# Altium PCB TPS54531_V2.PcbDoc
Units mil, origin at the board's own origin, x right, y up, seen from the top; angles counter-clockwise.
Board outline 1035 x 775 mil, 2 copper layers (Top Layer, Bottom Layer); 21 components, 10 nets, 49 pads, 25 vias.
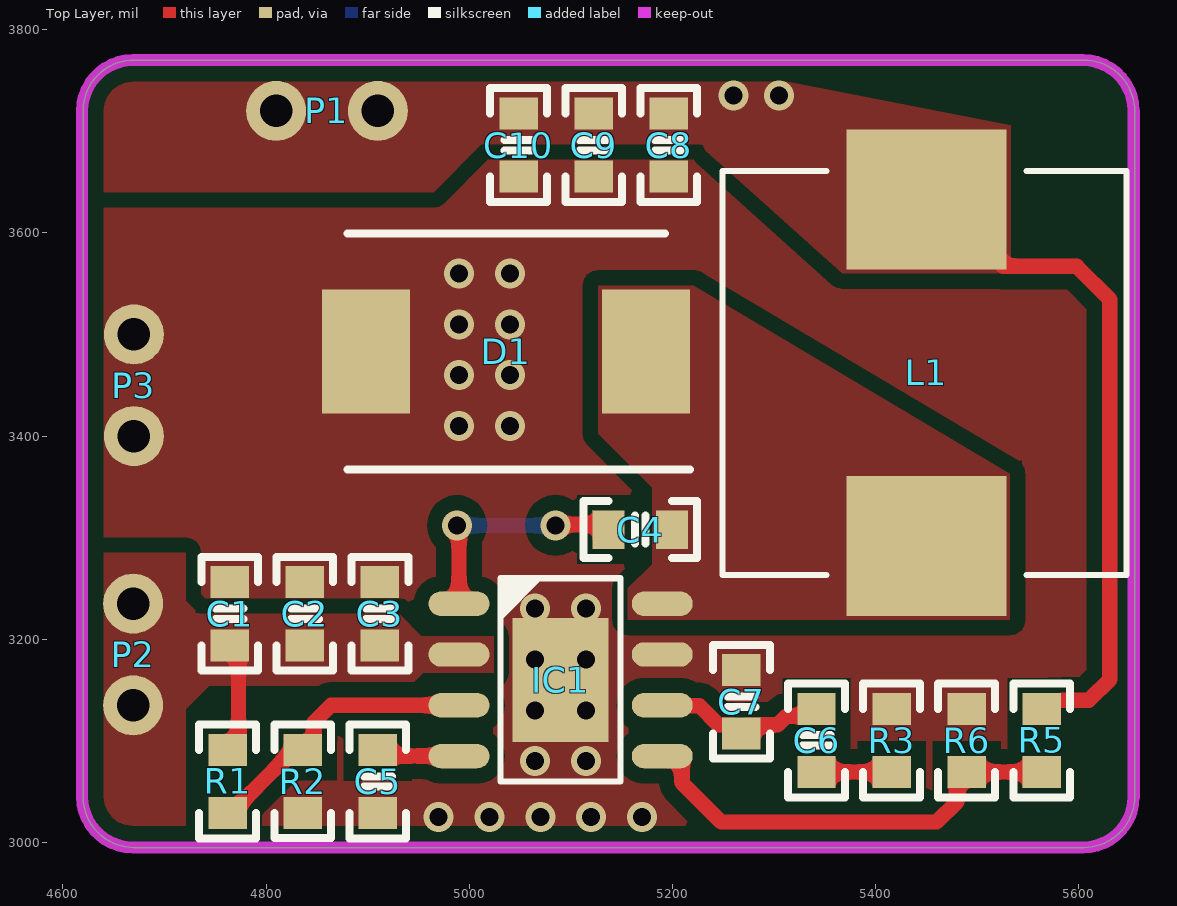
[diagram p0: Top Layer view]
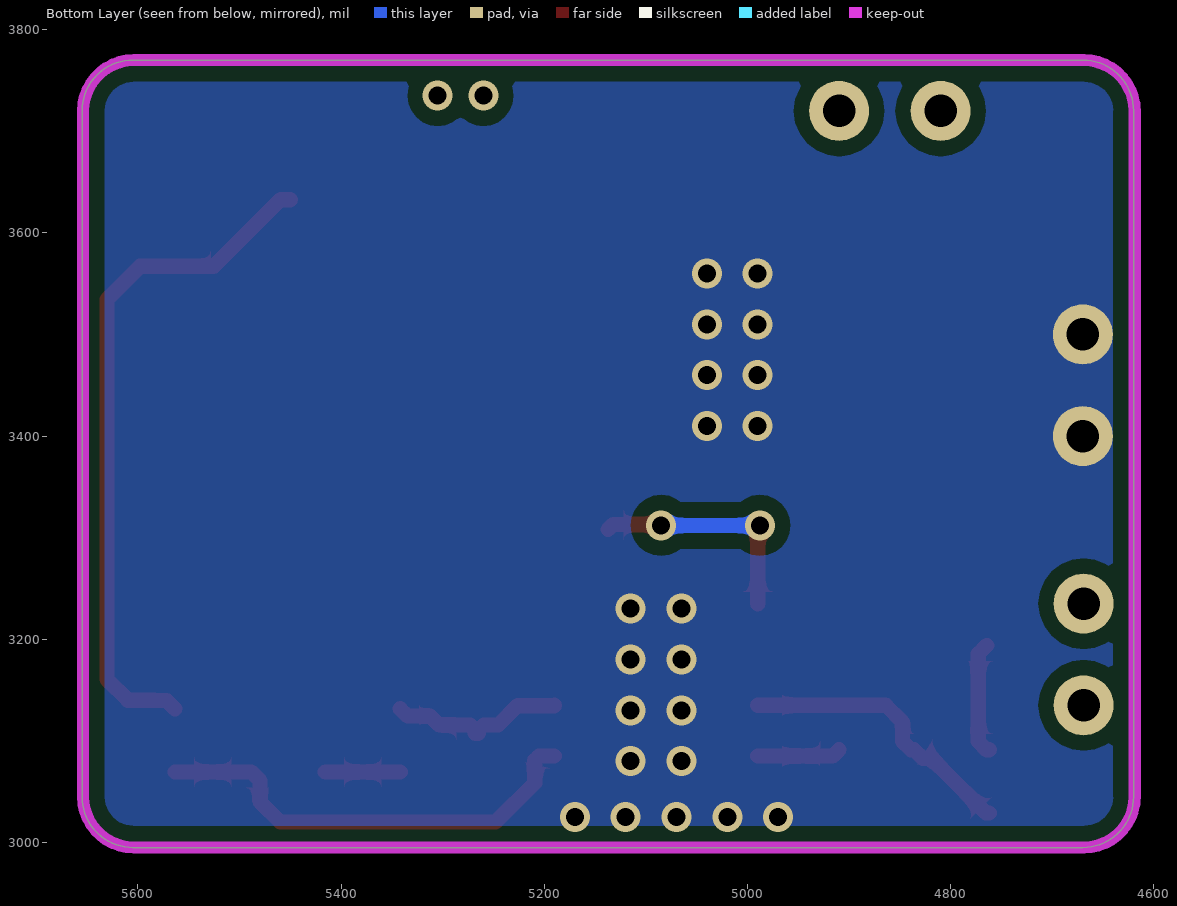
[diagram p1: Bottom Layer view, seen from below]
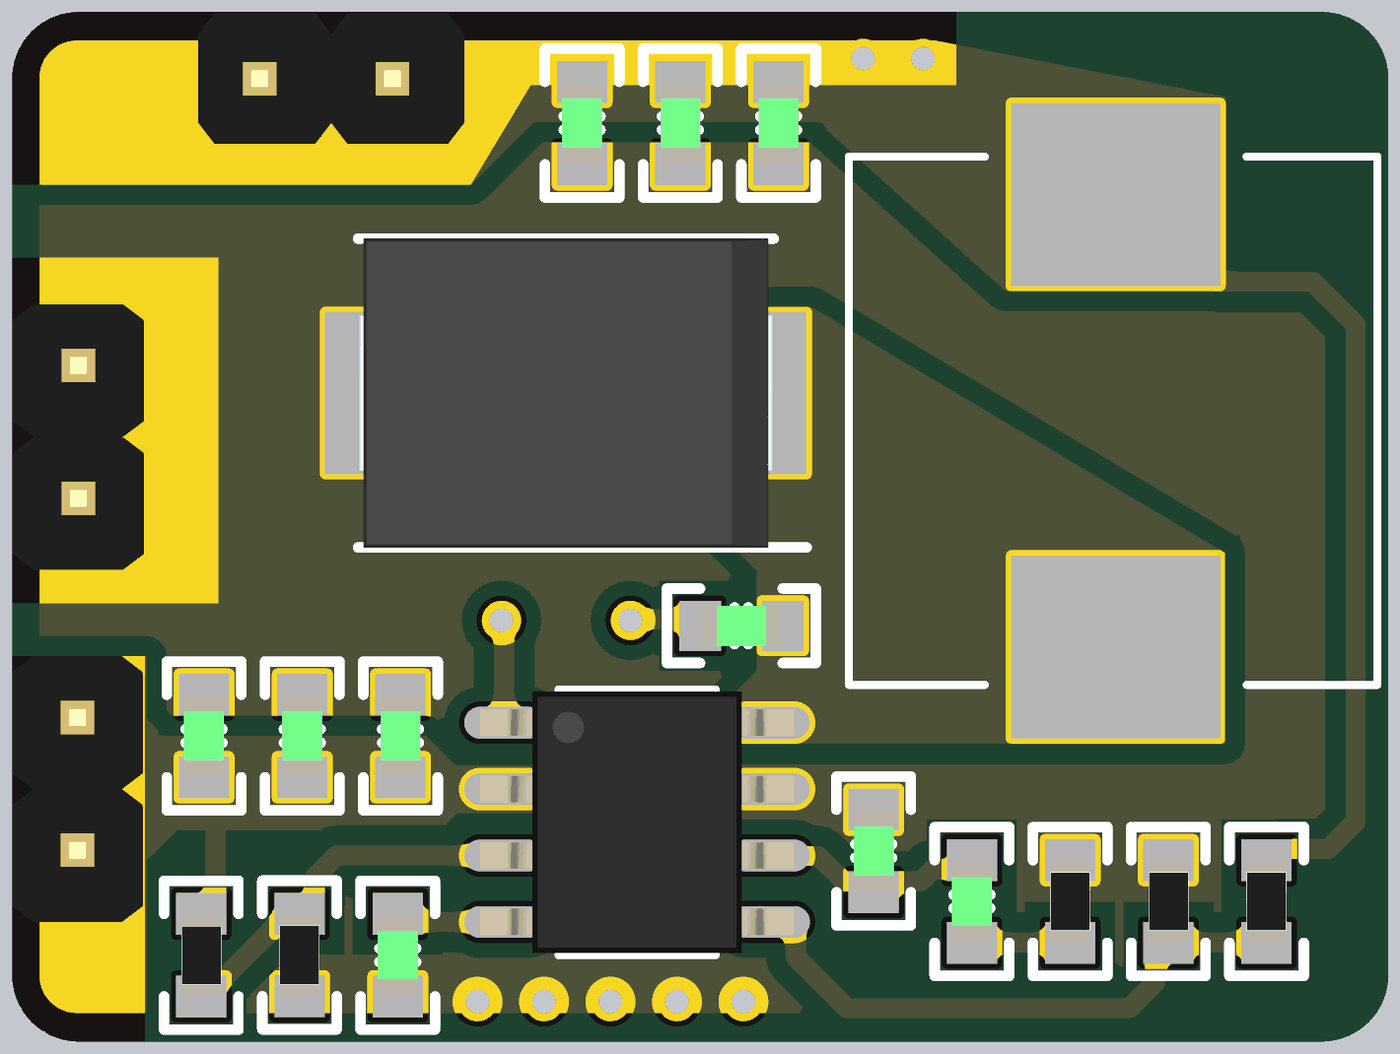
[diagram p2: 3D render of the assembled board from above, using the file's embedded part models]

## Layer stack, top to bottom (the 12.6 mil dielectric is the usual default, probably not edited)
Top Solder: solder mask 0.4, Solder Resist, Dk 3.5
Top Layer: signal copper 1.4
Dielectric 1: dielectric 12.6, FR-4, Dk 4.8
Bottom Layer: signal copper 1.4
Bottom Solder: solder mask 0.4, Solder Resist, Dk 3.5

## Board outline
4620,3045 ccw(c4670,3045) 4670,2995 4780,2995 5605,2995 ccw(c5605,3045) 5655,3045 5655,3720 ccw(c5605,3720) 5605,3770 4670,3770 ccw(c4670,3720) 4620,3720

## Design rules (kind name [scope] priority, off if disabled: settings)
Clearance [All] p1: gap=10 ignorepadtopadclearanceinfootprint=FALSE except(0: Arc-Hole Track-Hole SMDPad-Hole THPad-Hole Via-Hole Fill-Hole Poly-Hole Region-Hole Text-Hole; 15: Arc-Fill Arc-Poly Arc-Region Track-Fill Track-Poly Track-Region SMDPad-Fill SMDPad-Poly SMDPad-Region THPad-Fill THPad-Poly THPad-Region Via-Fill Via-Poly Via-Region Fill-Fill Fill-Poly Fill-Region Poly-Poly Poly-Region Region-Region)
PlaneConnect [All] p1: planeconnectstyle=Direct reliefexpansion=20 reliefentries=4 reliefconductorwidth=10 reliefairgap=10
PolygonConnect [All] p1: connectstyle=Direct reliefconductorwidth=10 reliefentries=4 polygonreliefangle="90 Angle" airgapwidth=10
RoutingVias [All] p1: holewidth=17.72 width=29.53 viastyle="Through Hole" minholewidth=17.72 minwidth=29.53 maxholewidth=17.72 maxwidth=29.53
SolderMaskExpansion [All] p1: expansion=4 istentingtop=FALSE
Width [All] p1: maxlimit=100 minlimit=10 preferedwidth=15
29 further rules are at their usual default settings.

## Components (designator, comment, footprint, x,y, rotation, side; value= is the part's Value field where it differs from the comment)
C1 "4.7uF" CAP-0603 4764.28,3225 r270 top
C2 "4.7uF" CAP-0603 4838.17,3225 r270 top
C3 "100nF" CAP-0603 4912.05,3225 r270 top
C4 "100nF" CAP-0603 5168.44,3307.95 r0 top
C5 "10nF" CAP-0603 4910,3060 r90 top
C6 "2200pF" CAP-0603 5341.83,3100.42 r90 top
C7 "22pF" CAP-0603 5267.95,3138.42 r270 top
C8 "47uF" CAP-0603 5196.44,3686.38 r90 top
C9 "47uF" CAP-0603 5122.55,3686.38 r90 top
C10 "100nF" CAP-0603 5048.67,3686.38 r90 top
D1 "SS54" DO-214AB 5036.45,3483.16 r180 top
IC1 "TPS54531DDA" SOIC_8_PAD 5090,3160 r270 top
L1 "4.7uH 5A" L-10040 5450,3462.31 r90 top
P1 "HDR1x2_2.54" HDR1X2_2.54_180 4810,3720 r90 top
P2 "HDR1x2_2.54" HDR1X2_2.54_180 4669.28,3235 r0 top
P3 "HDR1x2_2.54" HDR1X2_2.54_180 4670,3500 r0 top
R1 "665k" R-0603 4762.23,3060 r90 top
R2 "130k" R-0603 4836.12,3060.12 r90 top
R3 "37.4k" R-0603 5415.72,3100.42 r270 top
R5 "10.2k" R-0603 5563.48,3100.42 r90 top
R6 "1.96k" R-0603 5489.6,3100.42 r270 top

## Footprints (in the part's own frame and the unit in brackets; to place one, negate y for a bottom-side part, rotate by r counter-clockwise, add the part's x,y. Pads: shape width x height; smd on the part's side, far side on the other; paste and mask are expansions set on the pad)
CAP-0603 [mm]
  rect 0.8x0.96 smd: 1(-0.79,0) 2(0.79,0)
  silkscreen extent -1.42,-0.71 1.42,0.71, body extent -0.76,-0.39 0.76,0.39, height 0.9
DO-214AB [mm]
  rect 2.2x3.1 smd: 1(3.5,0) 2(-3.5,0)
  silkscreen extent -4.6,-2.95 3.97,2.95, body extent -3.97,-2.95 3.97,2.95, height 2.5
HDR1X2_2.54_180 [mm]
  round 1.5 hole 0.813: 1(0,0) 2(0,-2.54)
  body extent -1.25,-3.81 1.25,1.27, height 8.2
L-10040 [mm] "10.1*11.6*4.0MM(长*宽*高)"
  rect 3.5x4 smd: 1(-4.326,0) 2(4.326,0)
  silkscreen extent -5.05,-5 5.05,5.1, body extent -5,-5 5,5.08, height 4
R-0603 [mm]
  rect 0.8x0.96 smd: 1(-0.79,0) 2(0.79,0)
  silkscreen extent -1.42,-0.71 1.42,0.71, body extent -0.76,-0.38 0.76,0.38, height 0.41
SOIC_8_PAD [mil]
  oval 24x60 smd: 1(-75,-100) 2(-25,-100) 3(25,-100) 4(75,-100) 5(75,100) 6(25,100) 7(-25,100) 8(-75,100)
  rect 122.05x94.49 smd: 9(0,0)
  silkscreen extent -100,-59 100,59, body extent -98,-118 98,118, height 71

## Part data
C1 C2 C3 C4 C5 C6 C7 C8 C9 C10: library part CAP, "贴片电容", Package=0402, SuppliersPartNumber=C52923
D1: library part DIODE, "肖特基二极管", Package=SMA(DO-214AC), SuppliersPartNumber=C22452
IC1: "集成稳压芯片", Manufacturer_Name="Texas Instruments", Mouser Part Number=595-TPS54531DDA
L1: library part INDUCTOR, "电感", Package=0402, SuppliersPartNumber=C32041
P1 P2 P3: "Header"
R1 R2 R3 R5 R6: library part RES, "贴片电阻", Package=0805, SuppliersPartNumber=C17798

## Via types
v1: diameter 29.53, hole 17.72, Top Layer to Bottom Layer, 25 vias

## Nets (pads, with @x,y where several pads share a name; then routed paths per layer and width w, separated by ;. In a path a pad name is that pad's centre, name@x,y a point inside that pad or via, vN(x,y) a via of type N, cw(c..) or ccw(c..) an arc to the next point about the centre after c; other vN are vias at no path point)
5V: C8.2 C9.2 C10.2 L1.2 P1.1 P1.2 R5.2 | length 674.2
  Top Layer w15: L1.2 5459.84,3632.63 5525.47,3567 5598,3567 5630.5,3534.5 5630.5,3160.5 5610,3140 5583.67,3140 5583.43,3139.77 5571.73,3139.77 R5.2
  other v1: 5260,3735 5305,3735
GND: C1.1 C2.1 C3.1 C5.1 C7.1 C8.1 C9.1 C10.1 D1.1 IC1.7 IC1.9 P3.1 P3.2 R2.1 R3.1 R6.1
  other v1: 4970,3025 5020,3025 5070,3025 5120,3025 5170,3025 5065,3080 5115,3080 5065,3130 5115,3130 5065,3180 5115,3180 5065,3230 5115,3230 4990,3410 5040,3410 4990,3460 5040,3460 4990,3510 5040,3510 4990,3560 5040,3560
NetC4_1: C4.1 IC1.1 | length 229.7
  Top Layer w15: v1(4988,3312) 4990,3310 IC1.1 ; v1(5085,3312) 5086,3313 5132.28,3313 C4.1
  Bottom Layer w15: v1(4988,3312) v1(5085,3312)
NetC4_2: C4.2 D1.2 IC1.8 L1.1
NetC5_2: C5.2 IC1.4 | length 82.5
  Top Layer w15: C5.2 4916.1,3085 IC1.4
NetC6_1: C6.1 R3.2 | length 73.9
  Top Layer w15: C6.1 R3.2
NetC6_2: C6.2 C7.2 IC1.6 | length 176.5
  Top Layer w15: IC1.6 5190.4,3134.6 5226.4,3134.6 5245.44,3115.56 5259.7,3115.56 C7.2 ; C7.2@5264.8,3107.31 5273.05,3115.56 5303.56,3115.56 5312.44,3124.44 5334.75,3124.44 C6.2
NetIC1_3: IC1.3 R1.1 R2.2 | length 282.9
  Top Layer w15: R1.1 4765.38,3028.9 4819.45,3082.97 4827.87,3082.97 R2.2 4839.27,3091.22 4847.51,3099.47 4847.51,3118.51 4864,3135 IC1.3
NetIC1_5: IC1.5 R5.1 R6.2 | length 446.3
  Top Layer w15: IC1.5 5205.34,3085 5209.5,3080.84 5209.5,3058.5 5248,3020 5460,3020 5480,3040 5480,3061.06 5488.25,3069.31 R6.2 R5.1
VM: C1.2 C2.2 C3.2 IC1.2 P2.1 P2.2 R1.2 | length 112.6
  Top Layer w15: R1.2 4764.75,3091.1 4773,3099.35 4773,3185.65 4764.75,3193.9 C1.2

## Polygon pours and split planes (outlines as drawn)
GND on Top Layer "NONET_L01_P-001" (solid, remove dead copper, pour order 5): 4125,4035 4125,2430 6430,2430 6430,4105
VM on Top Layer "NONET_L01_P-001" (solid, pour order 1): 4621,3285 4621,2995 4721,2995 4721,3131 4744,3154 4942,3154 4955,3167 5024,3167 5024,3203 4953,3203 4931,3225 4734,3225 4721,3238 4721,3285
5V on Top Layer "NONET_L01_P-001" (solid, pour order 4): 5012,3687 4965,3640 4620,3640 4620,3770 5203.24,3770 5533,3706 5533,3560 5367,3560 5226,3687
NetC4_2 on Top Layer "NONET_L01_P-001" (solid, pour order 0): 5156,3219 5532,3219 5532,3363 5221,3548 5127,3548 5127,3402 5180,3349 5180,3274 5156,3250
5V on Top Solder "NONET_L01_P-001" (solid): 5330,3770 5330,3715 5010,3715 4965,3640 4619,3640 4619,3720 cw(c4669,3720) 4669,3770
GND on Top Solder "NONET_L01_P-001" (solid): 4620,3325 4775,3325 4775,3585 4620,3585
VM on Top Solder "NONET_L01_P-001" (solid): 4720,3285 4720,2995 4669,2995 cw(c4669,3044) 4620,3044 4620,3285
5V on Bottom Solder "NONET_L01_P-001" (solid): 4965,3640 4619,3640 4619,3720 cw(c4669,3720) 4669,3770 4965,3770
GND on Bottom Solder "NONET_L01_P-001" (solid): 4620,3325 4775,3325 4775,3585 4620,3585
no net on Bottom Solder "NONET_L01_P-001" (solid): 4719.91,3285 4719.91,2995 4668.91,2995 cw(c4668.91,3044) 4619.91,3044 4619.91,3285
GND on Bottom Layer "NONET_L01_P-001" (solid, remove dead copper, pour order 6): 4114.96,4051.41 4114.96,2446.41 6419.96,2446.41 6419.96,4121.41

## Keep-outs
Keep-Out Layer:
  lines w12: 4619,3045 ccw(c4669,3045) 4669,2995 4779,2995 5604,2995 ccw(c5604,3045) 5654,3045 5654,3700 5654,3720 ccw(c5604,3720) 5604,3770 4669,3770 ccw(c4669,3720) 4619,3720 4619,3670 4619,3045

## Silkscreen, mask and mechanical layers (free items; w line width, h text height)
Mechanical 1:
  lines w12: 4620,3045 ccw(c4670,3045) 4670,2995 4780,2995 5605,2995 ccw(c5605,3045) 5655,3045 5655,3700 5655,3720 ccw(c5605,3720) 5605,3770 4670,3770 ccw(c4670,3720) 4620,3720 4620,3670 4620,3045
